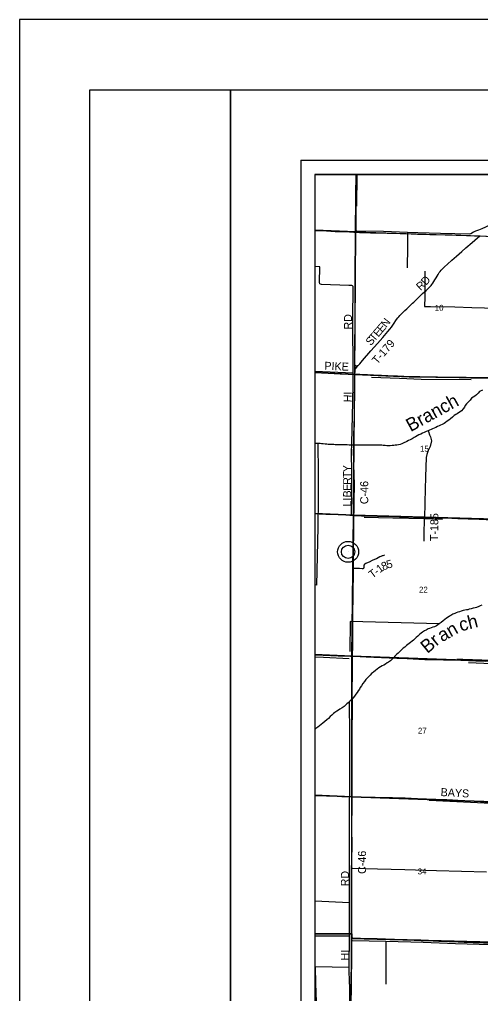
# Model space of a CAD drawing. Extents: x 0 to 39.4, y 0 to 22.
# Drawn here: x 0 to 3.28, y 15.08 to 22 of the extents above; entities that cross this region are included whole.
import ezdxf

# ---------------------------------------------------------------- set-up
doc = ezdxf.new("R2010")
doc.units = 0
for name, color, linetype in [('Default', 7, 'Continuous'), ('GM_X_County_Road', 7, 'Continuous'), ('GM_X_County_Road_Text', 7, 'Continuous'), ('GM_X_Interstate_Route', 7, 'Continuous'), ('GM_X_Major_River', 7, 'Continuous'), ('GM_X_Major_River_Text', 7, 'Continuous'), ('GM_X_Minor_River', 7, 'Continuous'), ('GM_X_Section', 7, 'Continuous'), ('GM_X_Section_Text', 7, 'Continuous'), ('GM_X_State_Route', 7, 'Continuous'), ('GM_X_Township_Road', 7, 'Continuous'), ('GM_X_Township_Road_Text', 7, 'Continuous'), ('GM_X_Unincorporated', 7, 'Continuous'), ('GM_X_Unincorporated_Location', 7, 'Continuous'), ('SH_Border', 7, 'Continuous'), ('SH_Cut_Line', 7, 'Continuous'), ('SH_Data', 7, 'Continuous')]:
    doc.layers.add(name, color=color, linetype=linetype)

msp = doc.modelspace()

# ---------------------------------------------------------------- linework, layer by layer
at = {"layer": 'Default'}
for points in [[(2.3931, 20.9), (2.1, 20.9), (2.1, 20.5038), (2.3906, 20.4913)], [(3.4024, 20.9), (2.3931, 20.9), (2.3906, 20.4913), (3.3917, 20.4596)], [(2.1, 20.5038), (2.1, 19.4929), (2.3842, 19.4785), (2.3906, 20.4913)], [(2.1, 19.4929), (2.1, 18.4918), (2.3742, 18.4805), (2.3842, 19.4785)], [(2.1, 18.4918), (2.1, 17.4902), (2.3633, 17.4784), (2.3742, 18.4805)], [(2.1, 17.4902), (2.1, 16.4913), (2.3619, 16.4807), (2.3633, 17.4784)], [(2.1, 16.4913), (2.1, 15.5089), (2.3594, 15.5066), (2.3619, 16.4807)], [(2.1, 15.5089), (2.1, 14.5256), (2.3556, 14.5215), (2.3597, 15.4744), (2.3594, 15.5066)]]:
    msp.add_lwpolyline(points, close=True, dxfattribs=at)
at = {"layer": 'GM_X_County_Road'}
msp.add_line((2.3624, 15.4997), (2.3624, 15.5064), dxfattribs=at)
for points in [[(2.3886, 20.4827), (2.3886, 20.4893), (2.3887, 20.514), (2.3895, 20.5792), (2.3899, 20.6445), (2.3912, 20.7502), (2.3932, 20.9)], [(2.3849, 19.5364), (2.3849, 19.5434), (2.3848, 19.5504), (2.3844, 19.6002), (2.3841, 19.6468), (2.3842, 19.709), (2.3851, 19.8208), (2.3854, 19.8954), (2.3853, 19.9794), (2.3852, 20.0104), (2.3852, 20.054), (2.3854, 20.1317), (2.3861, 20.2032), (2.3868, 20.2778), (2.3881, 20.3617), (2.3885, 20.4176), (2.3886, 20.4798), (2.3886, 20.4827)], [(2.3843, 19.4743), (2.3844, 19.4813), (2.3849, 19.5007), (2.3849, 19.5096)], [(2.3849, 19.5096), (2.385, 19.5166), (2.385, 19.5194), (2.3849, 19.5364)], [(2.3771, 18.4711), (2.3772, 18.478), (2.3778, 18.5063), (2.3784, 18.5529), (2.3792, 18.6057), (2.3801, 18.671), (2.3803, 18.7207), (2.3798, 18.7456), (2.3781, 18.786), (2.3768, 18.8202), (2.3757, 18.8699), (2.3752, 18.932), (2.3757, 18.9693), (2.376, 18.9973), (2.3771, 19.0439), (2.3795, 19.1184), (2.3813, 19.1743), (2.3819, 19.2148), (2.3821, 19.2583), (2.3825, 19.3205), (2.3832, 19.4261), (2.3843, 19.4743)], [(2.1, 18.4917), (2.1308, 18.4904), (2.1774, 18.4879), (2.2643, 18.4839), (2.3202, 18.4811), (2.3481, 18.4796), (2.3772, 18.478)], [(2.3732, 18.0968), (2.3733, 18.1036), (2.3738, 18.1426), (2.3742, 18.1893), (2.3746, 18.2234), (2.3749, 18.267), (2.3756, 18.3229), (2.3762, 18.4099), (2.3765, 18.4379), (2.3767, 18.4503), (2.3771, 18.4711)], [(2.3772, 18.478), (2.3853, 18.4775), (2.4319, 18.476), (2.4661, 18.4752), (2.5158, 18.4742), (2.5438, 18.4735), (2.6059, 18.4718), (2.6556, 18.4704), (2.7022, 18.4691), (2.7613, 18.4676), (2.7773, 18.4672), (2.8004, 18.4666), (2.8222, 18.4661), (2.8361, 18.4657), (2.8576, 18.4652), (2.8786, 18.4644)], [(2.8786, 18.4644), (2.9228, 18.4628), (2.9539, 18.462), (3.0098, 18.4606), (3.072, 18.4587), (3.1154, 18.4571), (3.1558, 18.4554), (3.1899, 18.4543), (3.2179, 18.4534), (3.2676, 18.4514), (3.3172, 18.4491), (3.339, 18.4481), (3.3762, 18.4463), (3.3797, 18.4462)], [(2.3666, 17.4704), (2.3665, 17.4714), (2.3666, 17.4775), (2.3666, 17.4869), (2.3672, 17.5024), (2.3683, 17.5303), (2.3688, 17.5614), (2.369, 17.636), (2.3696, 17.7168), (2.3697, 17.7666), (2.3701, 17.8163), (2.3708, 17.866), (2.372, 17.9562), (2.373, 18.0432), (2.373, 18.0743), (2.3732, 18.0929), (2.3732, 18.0968)], [(2.3643, 16.473), (2.3644, 16.48), (2.3644, 16.483), (2.3642, 16.5544), (2.3651, 16.7316), (2.3651, 16.7782), (2.3656, 16.8715), (2.3658, 16.9305), (2.3658, 16.9865), (2.3662, 17.0611), (2.3663, 17.1264), (2.3662, 17.1637), (2.3657, 17.2041), (2.3658, 17.2538), (2.3661, 17.3346), (2.3665, 17.403), (2.3667, 17.4434), (2.3666, 17.4704)], [(2.3624, 15.5064), (2.3622, 15.6003), (2.3626, 15.6376), (2.3625, 15.6624), (2.3627, 15.6997), (2.3628, 15.765), (2.3631, 15.8551), (2.3632, 15.9049), (2.3634, 15.9763), (2.3633, 16.0292), (2.3638, 16.1411), (2.3632, 16.2499), (2.3634, 16.3213), (2.3635, 16.368), (2.3636, 16.4053), (2.3643, 16.473)], [(2.3625, 15.4768), (2.3624, 15.4977), (2.3624, 15.4997)], [(2.3571, 14.5167), (2.3571, 14.5187), (2.3571, 14.5241), (2.3577, 14.6523), (2.3578, 14.7331), (2.3581, 14.8015), (2.3581, 14.8575), (2.3583, 14.9196), (2.3583, 14.988), (2.3587, 15.0315), (2.3602, 15.1061), (2.361, 15.1714), (2.3611, 15.2087), (2.3615, 15.2988), (2.3622, 15.3796), (2.3622, 15.4324), (2.3625, 15.4698)], [(2.3625, 15.4698), (2.3625, 15.4728), (2.3625, 15.4768)]]:
    msp.add_lwpolyline(points, dxfattribs=at)
at = {"layer": 'GM_X_Interstate_Route'}
for points in [[(5.4327, 20.9), (2.1, 20.9), (2.1, 15.507), (2.138, 15.5069), (2.2095, 15.507), (2.2857, 15.5069), (2.3463, 15.5066), (2.3581, 15.5068), (2.3622, 15.5069), (2.3622, 15.4983), (2.3622, 15.4774), (2.3691, 15.4771), (2.4234, 15.4748), (2.543, 15.4709), (2.6005, 15.4693), (2.6658, 15.4672), (2.7559, 15.4644), (2.8537, 15.4609), (2.8972, 15.4594), (2.9795, 15.4558), (3.0509, 15.4528), (3.1177, 15.4503), (3.1612, 15.4485), (3.2233, 15.4465), (3.2979, 15.4439)], [(3.2979, 15.4439), (3.2233, 15.4465), (3.1612, 15.4485), (3.1177, 15.4503), (3.0509, 15.4528), (2.9795, 15.4558), (2.8972, 15.4594), (2.8537, 15.4609), (2.7559, 15.4644), (2.6658, 15.4672), (2.6005, 15.4693), (2.543, 15.4709), (2.4234, 15.4748), (2.3691, 15.4771), (2.3622, 15.4774), (2.3622, 15.4983), (2.3622, 15.5069), (2.3581, 15.5068), (2.3463, 15.5066), (2.2857, 15.5069), (2.2095, 15.507), (2.138, 15.5069), (2.1, 15.507), (2.1, 14.1)]]:
    msp.add_lwpolyline(points, dxfattribs=at)
at = {"layer": 'GM_X_Major_River'}
for points in [[(3.2905, 19.3676), (3.2707, 19.357), (3.2605, 19.3452), (3.2483, 19.3339), (3.2365, 19.3256), (3.2255, 19.3184), (3.2137, 19.3097), (3.2023, 19.2975), (3.1905, 19.2843), (3.1779, 19.2707), (3.1684, 19.2578), (3.1634, 19.2475), (3.1546, 19.2339), (3.1428, 19.2214), (3.1322, 19.2142), (3.1204, 19.207), (3.1109, 19.2002), (3.101, 19.1949), (3.0889, 19.187), (3.0767, 19.1752), (3.0637, 19.1635), (3.0527, 19.1556), (3.0398, 19.1465), (3.0276, 19.1385), (3.0177, 19.1314), (3.0044, 19.1242), (2.9923, 19.1185), (2.982, 19.1136), (2.9706, 19.1091), (2.9585, 19.103), (2.9471, 19.0981), (2.9364, 19.0932), (2.925, 19.0883), (2.9148, 19.0842), (2.9053, 19.0789), (2.8908, 19.0729), (2.8764, 19.0665), (2.865, 19.0619), (2.8524, 19.0559), (2.8391, 19.0495), (2.8262, 19.0431), (2.8145, 19.037), (2.8042, 19.0313), (2.7905, 19.0226), (2.778, 19.0151), (2.7647, 19.009), (2.7544, 19.0038), (2.7278, 18.9902), (2.7179, 18.9864), (2.7065, 18.9826), (2.6932, 18.9796), (2.683, 18.9778), (2.6697, 18.9763), (2.6602, 18.9752), (2.6486, 18.9741), (2.6359, 18.9732), (2.6253, 18.9726), (2.612, 18.973), (2.5984, 18.9746), (2.5855, 18.9758), (2.5745, 18.9762), (2.5604, 18.9766), (2.5384, 18.9767), (2.5244, 18.9771), (2.5104, 18.9768), (2.5009, 18.9772), (2.4887, 18.9772), (2.4781, 18.9776), (2.4671, 18.978), (2.4527, 18.9777), (2.4424, 18.9773), (2.4311, 18.9766), (2.417, 18.9763), (2.4068, 18.9767), (2.3973, 18.9767), (2.3867, 18.9764), (2.3593, 18.9765), (2.3438, 18.9776)], [(2.3438, 18.9776), (2.3289, 18.9788), (2.3168, 18.9794), (2.3067, 18.9794), (2.2969, 18.9797), (2.2865, 18.9801), (2.2668, 18.9801), (2.2528, 18.9802), (2.2441, 18.9805), (2.2352, 18.9808), (2.2231, 18.9817), (2.2112, 18.9819), (2.1951, 18.9822), (2.1848, 18.983), (2.1723, 18.9838), (2.1575, 18.9854), (2.1458, 18.987), (2.1363, 18.9881), (2.126, 18.9889), (2.1116, 18.9893), (2.1, 18.989)], [(3.1666, 17.8052), (3.1529, 17.8022), (3.14, 17.7985), (3.1267, 17.7936), (3.1164, 17.7906), (3.1047, 17.7864), (3.094, 17.7823), (3.0796, 17.7759), (3.0663, 17.7683), (3.0556, 17.7615), (3.0461, 17.7558), (3.0363, 17.749), (3.0226, 17.7384), (3.0108, 17.7286), (2.9971, 17.7176), (2.9834, 17.7074), (2.9731, 17.7006), (2.9629, 17.6942), (2.9503, 17.6881), (2.9374, 17.6836), (2.9268, 17.6802), (2.9139, 17.6761), (2.904, 17.6723), (2.8911, 17.6636), (2.8785, 17.6576), (2.8648, 17.6485), (2.8542, 17.6413), (2.8428, 17.633), (2.831, 17.6209), (2.8207, 17.6118), (2.8112, 17.6023), (2.8013, 17.5932), (2.7911, 17.5849), (2.7796, 17.5754), (2.7698, 17.5682), (2.7603, 17.5611), (2.75, 17.5542), (2.7382, 17.5433), (2.7279, 17.5346), (2.7158, 17.5236), (2.7043, 17.5118), (2.6922, 17.5009), (2.6819, 17.4918), (2.669, 17.4785), (2.6602, 17.4683), (2.6495, 17.4569), (2.6374, 17.4463), (2.6237, 17.4365), (2.613, 17.4301), (2.6013, 17.4229), (2.5887, 17.4157), (2.5788, 17.4108), (2.5667, 17.4036), (2.5553, 17.3953), (2.5427, 17.387), (2.5294, 17.3764), (2.5169, 17.3658), (2.5028, 17.3548), (2.4925, 17.3438), (2.483, 17.3347), (2.4731, 17.3237), (2.4628, 17.3131), (2.4525, 17.2998), (2.44, 17.2835), (2.4301, 17.268), (2.4217, 17.2551), (2.416, 17.2449), (2.4076, 17.232), (2.4011, 17.2217), (2.3908, 17.2081), (2.382, 17.1948), (2.3729, 17.1827), (2.3596, 17.1691), (2.3501, 17.1607), (2.3367, 17.1478), (2.3272, 17.1399), (2.3177, 17.1316), (2.3071, 17.1221), (2.293, 17.1107), (2.2782, 17.1021), (2.2675, 17.0949), (2.2558, 17.0873), (2.2424, 17.0775), (2.2326, 17.0707), (2.22, 17.0608), (2.2086, 17.0498), (2.196, 17.0366), (2.1842, 17.0267), (2.1694, 17.0135), (2.1569, 17.0021), (2.1451, 16.9923), (2.1333, 16.9832), (2.1196, 16.9734), (2.1074, 16.9639), (2.1, 16.9576)], [(3.2858, 17.8417), (3.2736, 17.8353), (3.2641, 17.8308), (3.2489, 17.8247), (3.2383, 17.8217), (3.2246, 17.8183), (3.2095, 17.815), (3.1966, 17.812), (3.1871, 17.8086), (3.1776, 17.8067), (3.1666, 17.8052)]]:
    msp.add_lwpolyline(points, dxfattribs=at)
at = {"layer": 'GM_X_Minor_River'}
for p, q in [((2.398, 20.6749), (2.4004, 20.9)), ((2.3708, 19.4892), (2.1, 19.4994)), ((2.3454, 15.7278), (2.1, 15.7379))]:
    msp.add_line(p, q, dxfattribs=at)
for points in [[(3.3893, 20.9), (3.3877, 20.8543), (3.3868, 20.6974), (3.3835, 20.5843), (3.3818, 20.544), (3.3723, 20.5406), (3.3594, 20.5391), (3.3496, 20.5388), (3.3313, 20.535), (3.3123, 20.5248), (3.2869, 20.5128), (3.2626, 20.5045), (3.2424, 20.4977), (3.228, 20.4905), (3.2071, 20.4769), (3.1965, 20.4762), (2.9935, 20.4806), (2.8319, 20.4845), (2.7583, 20.4866), (2.5868, 20.4939), (2.399, 20.4979)], [(2.7583, 20.4866), (2.7572, 20.3859), (2.7548, 20.2359)], [(2.3601, 18.4861), (2.3621, 18.6243), (2.3633, 18.7903), (2.3595, 18.9191), (2.3628, 18.992), (2.3694, 19.2822), (2.3717, 19.4128), (2.3708, 19.4892), (2.3705, 19.875), (2.3723, 20.0988), (2.3708, 20.1048), (2.3674, 20.1094), (2.3621, 20.1106), (2.3413, 20.1114), (2.1478, 20.1188), (2.1398, 20.1196), (2.136, 20.1219), (2.1323, 20.1321), (2.1338, 20.2438), (2.1, 20.2453)], [(2.8819, 20.2127), (2.8805, 20.1337), (2.8805, 20.03), (2.8792, 19.9628), (2.9205, 19.9619), (3.0951, 19.9588), (3.2157, 19.955), (3.3064, 19.9524), (3.3716, 19.9492), (3.4706, 19.947), (3.655, 19.9389), (3.8234, 19.9323), (4.0109, 19.9245), (4.1395, 19.9203), (4.3235, 19.916), (4.4418, 19.9145), (4.6683, 19.9107), (4.8691, 19.9098), (4.9609, 19.9087), (5.0834, 19.9068), (5.1464, 19.9048), (5.2027, 19.9034)], [(2.5028, 19.4599), (2.7015, 19.4525), (2.8544, 19.4467), (3.2111, 19.4441)], [(2.9053, 19.0789), (2.9083, 19.0729), (2.9154, 19.0515), (2.9203, 19.0352), (2.9278, 19.0067), (2.9193, 18.9683), (2.906, 18.9391), (2.8956, 18.9118), (2.8906, 18.8894), (2.8864, 18.7531), (2.8813, 18.5711), (2.8783, 18.453)], [(2.1215, 18.9891), (2.122, 18.7812), (2.1237, 18.5973), (2.1204, 18.3945), (2.1164, 18.1882), (2.1116, 17.9835), (2.1, 17.984)], [(3.0058, 18.4492), (2.8783, 18.453), (2.6541, 18.459), (2.4511, 18.4634)], [(2.9834, 17.7074), (2.351, 17.7237), (2.3485, 17.511)], [(2.1, 17.4736), (2.1605, 17.4709), (2.3434, 17.4624)], [(3.9851, 17.4305), (3.7178, 17.44), (3.3559, 17.4483), (3.1503, 17.4543), (3.1097, 17.4555)], [(3.4826, 17.427), (3.3544, 17.4248), (3.1905, 17.431)], [(2.3465, 15.1503), (2.3429, 15.2681), (2.3447, 15.4922), (2.3454, 15.7278), (2.3447, 15.9888), (2.3464, 16.3026), (2.3482, 16.6486), (2.3478, 16.9146), (2.3455, 17.1563)], [(3.8703, 16.4183), (3.6006, 16.426), (3.3521, 16.4325), (2.911, 16.4544)], [(3.3184, 15.9444), (2.9641, 15.9546), (2.7396, 15.961), (2.5446, 15.965), (2.3674, 15.9701)], [(2.1, 15.4934), (2.1133, 15.4933), (2.3447, 15.4922)], [(2.3674, 15.4606), (2.6034, 15.4542), (2.8693, 15.4478), (3.0996, 15.4379), (3.3492, 15.4322), (3.367, 15.4306), (3.6822, 15.4209), (3.8833, 15.4138), (4.0646, 15.411), (4.1609, 15.4054)], [(2.6034, 15.4542), (2.6041, 15.3118), (2.6044, 15.1499)], [(2.3429, 15.2681), (2.1009, 15.2718), (2.1038, 15.153)], [(2.1038, 15.153), (2.1096, 15.0244), (2.1096, 14.7743), (2.1, 14.7744)], [(2.3465, 15.1503), (2.3471, 14.7796), (2.3418, 14.1563), (2.3426, 14.1179)]]:
    msp.add_lwpolyline(points, dxfattribs=at)
at = {"layer": 'GM_X_Section'}
for points in [[(2.3906, 20.4913), (3.3917, 20.4596), (3.377, 19.4549), (2.7709, 19.4617), (2.3842, 19.4785)], [(2.3842, 19.4785), (2.7709, 19.4617), (3.377, 19.4549), (3.3817, 18.4522), (2.3742, 18.4805)], [(2.3742, 18.4805), (3.3817, 18.4522), (3.367, 17.4429), (2.3633, 17.4784)], [(2.3633, 17.4784), (3.367, 17.4429), (3.3671, 16.4448), (2.3619, 16.4807)], [(2.3619, 16.4807), (3.3671, 16.4448), (3.3623, 15.4472), (2.3597, 15.4744), (2.3594, 15.5066)], [(2.3597, 15.4744), (3.3623, 15.4472), (3.3836, 15.4465), (3.3725, 14.5132), (2.3556, 14.5215)]]:
    msp.add_lwpolyline(points, close=True, dxfattribs=at)
at = {"layer": 'GM_X_State_Route'}
msp.add_lwpolyline([(2.1, 17.4891), (2.1596, 17.4865), (2.2652, 17.4818), (2.3521, 17.4781), (2.3666, 17.4775), (2.4204, 17.4752), (2.4639, 17.4738), (2.5726, 17.469), (2.6813, 17.4643), (2.7558, 17.4615), (2.88, 17.4561), (3.0136, 17.4526), (3.1379, 17.4493), (3.1907, 17.4477), (3.2435, 17.446), (3.315, 17.4441)], dxfattribs=at)
at = {"layer": 'GM_X_Township_Road'}
msp.add_line((2.3624, 15.5064), (2.3624, 15.4997), dxfattribs=at)
for points in [[(2.1, 20.5019), (2.1285, 20.5007), (2.1813, 20.4983), (2.2434, 20.4955), (2.2962, 20.4934), (2.3459, 20.4909), (2.377, 20.4898), (2.3886, 20.4893)], [(2.3886, 20.4893), (2.4169, 20.4882), (2.4946, 20.4856), (2.6126, 20.4827), (2.6623, 20.4814), (2.7058, 20.4798), (2.7834, 20.4781), (2.83, 20.4764), (2.9169, 20.474), (2.9604, 20.4722), (3.0257, 20.4709), (3.0753, 20.4697), (3.122, 20.4686), (3.1375, 20.4682), (3.1778, 20.4667), (3.2057, 20.4654), (3.2337, 20.4643), (3.274, 20.4632)], [(2.4076, 19.5428), (2.418, 19.5548), (2.4383, 19.5783), (2.4976, 19.6462), (2.5447, 19.7), (2.5815, 19.7421), (2.618, 19.7845), (2.6319, 19.8013), (2.6432, 19.8161), (2.6576, 19.8363), (2.6804, 19.8697), (2.6895, 19.8823), (2.6953, 19.8895), (2.7036, 19.8988), (2.7123, 19.9077), (2.7392, 19.9335), (2.7527, 19.9463), (2.7863, 19.9788), (2.7931, 19.9851), (2.8021, 19.9937), (2.8273, 20.0167), (2.845, 20.0341), (2.8653, 20.0534), (2.8906, 20.0763), (2.9088, 20.0933), (2.9198, 20.1043), (2.926, 20.1113), (2.9317, 20.1186), (2.9369, 20.1264), (2.945, 20.1396), (2.9514, 20.1502), (2.961, 20.1663), (2.9758, 20.19), (2.9842, 20.203), (2.9897, 20.2105), (2.9975, 20.2202), (3.0037, 20.2271), (3.0103, 20.2337), (3.0216, 20.2444), (3.0424, 20.263), (3.0727, 20.2897), (3.1054, 20.3185), (3.145, 20.3535), (3.1732, 20.3778), (3.218, 20.4163), (3.2561, 20.4483), (3.268, 20.4582), (3.274, 20.4632)], [(3.274, 20.4632), (3.3144, 20.4613), (3.3671, 20.4591), (3.395, 20.458)], [(2.3849, 19.5434), (2.3893, 19.5422), (2.3925, 19.5414), (2.3959, 19.5411), (2.3992, 19.5414), (2.4025, 19.5419), (2.4076, 19.5428)], [(2.385, 19.5166), (2.3896, 19.5219), (2.3956, 19.529), (2.4076, 19.5428)], [(2.1, 19.493), (2.1218, 19.492), (2.1994, 19.4884), (2.2367, 19.4865), (2.2801, 19.4847), (2.3143, 19.483), (2.3422, 19.4818), (2.364, 19.4813), (2.3844, 19.4813)], [(2.3844, 19.4813), (2.3919, 19.4813), (2.4199, 19.4804), (2.4727, 19.4781), (2.5161, 19.4762), (2.572, 19.474), (2.6186, 19.4719), (2.6869, 19.469), (2.7801, 19.4654), (2.8453, 19.4635), (2.895, 19.4619), (2.9602, 19.4607), (2.9975, 19.46), (3.0348, 19.4594), (3.1249, 19.4576), (3.1684, 19.4567), (3.2088, 19.4559), (3.2834, 19.4546), (3.3704, 19.4527), (3.3818, 19.4524)], [(2.8762, 18.2957), (2.8772, 18.3131), (2.8771, 18.3385), (2.8774, 18.37), (2.878, 18.4288), (2.8781, 18.4485), (2.8785, 18.4614), (2.8786, 18.4644)], [(2.3733, 18.1036), (2.3777, 18.1037), (2.39, 18.1039), (2.3962, 18.1039), (2.4179, 18.1032), (2.4364, 18.102), (2.4397, 18.1019), (2.4411, 18.1019), (2.4426, 18.1022), (2.4441, 18.1026), (2.4454, 18.1031), (2.4463, 18.1038), (2.4471, 18.1044), (2.4478, 18.1052), (2.4484, 18.106), (2.4488, 18.1067), (2.4494, 18.1081), (2.4498, 18.1096), (2.45, 18.1112), (2.4511, 18.1237), (2.4513, 18.125), (2.4518, 18.1267), (2.4523, 18.1283), (2.4528, 18.1296), (2.4535, 18.1308), (2.4544, 18.1323), (2.4552, 18.1334), (2.4563, 18.1347), (2.4575, 18.1357), (2.4586, 18.1367), (2.46, 18.1377), (2.4612, 18.1385), (2.4625, 18.1393), (2.4639, 18.14), (2.4695, 18.1425), (2.4867, 18.1495), (2.5094, 18.1596), (2.5373, 18.173), (2.5624, 18.1853), (2.5708, 18.1891), (2.5793, 18.1927), (2.5852, 18.1946), (2.5912, 18.1963), (2.5941, 18.1971)], [(2.1, 16.4894), (2.1271, 16.4884), (2.183, 16.4862), (2.2606, 16.4836), (2.2917, 16.4822), (2.3134, 16.4815), (2.3644, 16.48)], [(2.3644, 16.48), (2.3849, 16.4793), (2.4626, 16.4782), (2.4936, 16.4771), (2.5278, 16.4763), (2.5931, 16.4749), (2.6521, 16.4741), (2.708, 16.473), (2.7422, 16.472), (2.8292, 16.469), (2.9596, 16.4636), (3.0373, 16.4602), (3.0776, 16.4579), (3.1149, 16.4557), (3.1738, 16.4524), (3.2111, 16.4505), (3.2762, 16.4467), (3.3383, 16.4429), (3.3636, 16.4419)], [(2.1, 15.5065), (2.1382, 15.5063), (2.2097, 15.5065), (2.2859, 15.5064), (2.3465, 15.506), (2.3583, 15.5063), (2.3624, 15.5064)], [(2.3624, 15.4997), (2.3624, 15.4977), (2.3625, 15.4768)], [(2.3625, 15.4768), (2.3693, 15.4766), (2.4237, 15.4742), (2.5433, 15.4704), (2.6008, 15.4687), (2.666, 15.4666), (2.7561, 15.4638), (2.854, 15.4603), (2.8974, 15.4588), (2.9797, 15.4552), (3.0512, 15.4523), (3.118, 15.4498), (3.1614, 15.4479), (3.2236, 15.4459), (3.2981, 15.4434), (3.3261, 15.4423), (3.3605, 15.4411)]]:
    msp.add_lwpolyline(points, dxfattribs=at)
at = {"layer": 'GM_X_Unincorporated'}
for radius in [0.0744, 0.0472]:
    msp.add_circle((2.3357, 18.2196), radius, dxfattribs=at)
at = {"layer": 'GM_X_Unincorporated_Location'}
msp.add_line((2.3357, 18.2196), (2.3357, 18.2196), dxfattribs=at)
at = {"layer": 'SH_Border'}
for points in [[(0.5, 21.5), (1.5, 21.5), (1.5, 0.5), (0.5, 0.5)], [(1.5, 21.5), (33.5, 21.5), (33.5, 0.5), (1.5, 0.5)]]:
    msp.add_lwpolyline(points, close=True, dxfattribs=at)
at = {"layer": 'SH_Cut_Line'}
msp.add_lwpolyline([(0, 0), (34, 0), (34, 22), (0, 22)], close=True, dxfattribs=at)
at = {"layer": 'SH_Data'}
for p, q in [((2, 21), (9, 21)), ((2, 21), (2, 14)), ((2.1, 20.9), (2.1, 14.1)), ((2.1, 20.9), (8.9, 20.9))]:
    msp.add_line(p, q, dxfattribs=at)

# ---------------------------------------------------------------- texts
at = {"layer": 'GM_X_County_Road_Text'}
for s, height, rotation, p in [('RD', 0.05682, 90, (2.3635, 19.7981)), ('HI', 0.05682, 89.41568, (2.361, 19.2808)), ('Y', 0.0568, 91.67955, (2.3566, 18.7867)), ('T', 0.0568, 91.92507, (2.358, 18.7443)), ('R', 0.0568, 90.00961, (2.358, 18.6956)), ('E', 0.0568, 89.54418, (2.3577, 18.6526)), ('C-46', 0.05682, 90, (2.4788, 18.5581)), ('B', 0.0568, 89.5358, (2.3573, 18.6059)), ('L', 0.0568, 89.53286, (2.3568, 18.5401)), ('I', 0.0568, 89.53165, (2.3571, 18.5826)), ('C-46', 0.05682, 90, (2.463, 15.9323)), ('RD', 0.05682, 90, (2.3418, 15.8439)), ('HI', 0.05682, 90, (2.341, 15.3181))]:
    msp.add_text(s, height=height, rotation=rotation, dxfattribs=at).set_placement(p)
at = {"layer": 'GM_X_Major_River_Text'}
for s, rotation, p in [('Branch', 28.9782, (2.7802, 19.0689)), ('ch', 14.45554, (3.1366, 17.6536)), ('an', 29.45852, (3.0037, 17.5767)), ('Br', 39.46063, (2.8987, 17.4936))]:
    msp.add_text(s, height=0.09474, rotation=rotation, dxfattribs=at).set_placement(p)
at = {"layer": 'GM_X_Section_Text'}
for s, p in [('10', (2.9518, 19.9315)), ('15', (2.8468, 18.9312)), ('22', (2.8397, 17.9301)), ('27', (2.8322, 16.9282)), ('34', (2.8305, 15.929))]:
    msp.add_text(s, height=0.04186, rotation=0.00001, dxfattribs=at).set_placement(p)
at = {"layer": 'GM_X_Township_Road_Text'}
for s, height, rotation, p in [('R', 0.0568, 42.75571, (2.8511, 20.0707)), ('D', 0.0568, 50.36899, (2.891, 20.1082)), ('N', 0.0568, 52.34969, (2.6078, 19.808)), ('E', 0.0568, 49.31376, (2.5503, 19.741)), ('E', 0.0568, 49.39418, (2.5781, 19.7733)), ('S', 0.0568, 49.30799, (2.4976, 19.6797)), ('T', 0.0568, 49.31089, (2.5226, 19.7087)), ('T-179', 0.05682, 48.97337, (2.5426, 19.5473)), ('PIKE', 0.05682, 357.57243, (2.1664, 19.5129)), ('T-185', 0.05682, 89.44197, (2.9754, 18.2954)), ('1', 0.0568, 35.95085, (2.561, 18.0671)), ('8', 0.0568, 23.31202, (2.5865, 18.086)), ('5', 0.0568, 16.14697, (2.6169, 18.0993)), ('T', 0.0568, 37.02846, (2.5087, 18.0277)), ('-', 0.0568, 36.86365, (2.5426, 18.0533)), ('BAYS', 0.05682, 356.91997, (2.9924, 16.4854))]:
    msp.add_text(s, height=height, rotation=rotation, dxfattribs=at).set_placement(p)

doc.saveas('drawing.dxf')
